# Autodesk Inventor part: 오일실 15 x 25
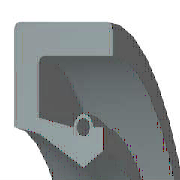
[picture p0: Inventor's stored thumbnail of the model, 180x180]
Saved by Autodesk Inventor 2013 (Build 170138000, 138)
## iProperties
IsCustomPart: 0
Created: 2015-10
Part Number: 오일실 15 x 25
Material: 고무
Description: 오일-실
Document SubType Name: Modeling
Standard: KS B 2804
Designer: mdu
Standards Organization: KS
Language: ko-KR
Size Designation: S - 15 25 7
Categories: <MemberInstance><Categories><Category DisplayName="샤프트 부품" InternalName="7f7aeb1f-a693-4053-b835-cee3144e0d98" Mnemonic="SHFT"><Category DisplayName="실링" Intern
Density: 0.93 g/cm^3
Author: mdu
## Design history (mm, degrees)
revolve "본체" stored, may be unused: angle "d17" = 90 deg
revolve "스프링1" stored, may be unused: angle "d18" = 90 deg
body "Solid1"
sketch "스케치1"
  geometry: L1 (0, 12.5)-(7, 12.5); L2 (7, 12.5)-(7, 11.25); L3 (7, 11.25)-(1.75, 11.25); L4 (0, 12.5)-(0, 9.6); L5 (0, 9.6)-(1.75, 9.25); L6 (1.75, 9.25)-(4.9, 7.5); L7 (4.9, 7.5)-(0, 7.5); L8 (6.3, 8.375)-(6.3, 9.6); L9 (0, 0)-(9.586, 0) reference; L10 (4.9, 7.5)-(6.3, 8.375); L11 (0, 18)-(0, -3) reference; L12 (-1.917, 0)-(11.503, 0) reference; L13 (4.2, 9.6)-(1.75, 10.09); L14 (1.75, 10.09)-(1.75, 11.25); L15 (6.3, 9.6)-(5.6, 9.6); C1 r 0.455 at (4.9, 9.6); A1 r 0.7 centre (4.9, 9.6) between (5.6, 9.6) and (4.2, 9.6)
  constraints: 26 end point, 5 horizontal alignment, 4 perpendicular, 2 centre point, 2 collinear, 2 horizontal, 2 parallel, 2 point on circle, 2 point on line, 2 vertical alignment, 1 coincident
  dimensions: "d0" = 25 diameter of L1 L9 (= SD2); "d1" = 16.75 diameter of L8.start L9 (= ABDM); "d2" = 1.25 distance of L1.end L2.end (computed from SD); "d3" = 0.91 diameter of C1 (= SPDI); "d4" = 1.4 diameter of A1 (= SPDA); "d5" = 15 diameter of L6.end L9 (= NND); "d6" = 18.5 diameter of L5.end L9 (= TKDM); "d7" = 19.2 diameter of L4.end L9 (= HLDM); "d8" = 4.9 distance from line of C1.centre L4 (= SPDST); "d9" = 6.3 distance between parallel lines of L8 L4 (= SDI); "d10" = 7 distance between parallel lines of L2 L4 (= SWDT); "d12" = 1.75 distance between parallel lines of L14 L4 (= SD)
fillet "모깎기1" dims "d11" = 0.3 (= RR)
other parameters: "SD2" = 25 [user parameter; used in 1 equation term], "SWDT" = 7 [user parameter; used in 1 equation term], "RR" = 0.3 [user parameter; used in 1 equation term], "SD" = 1.75 [user parameter; used in 2 equation terms], "NND" = 15 [user parameter; used in 1 equation term], "SPDA" = 1.4 [user parameter; used in 1 equation term], "SPDI" = 0.91 [user parameter; used in 1 equation term], "TKDM" = 18.5 [user parameter; used in 1 equation term], "HLDM" = 19.2 [user parameter; used in 1 equation term], "ABDM" = 16.75 [user parameter; used in 1 equation term], "SDI" = 6.3 [user parameter; used in 1 equation term], "SPDST" = 4.9 [user parameter; used in 1 equation term], "d13" = 0, "d14" = 0, "d15" = 0, "LAB" = 0.35 [user parameter]
